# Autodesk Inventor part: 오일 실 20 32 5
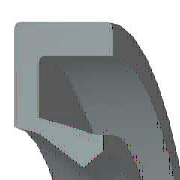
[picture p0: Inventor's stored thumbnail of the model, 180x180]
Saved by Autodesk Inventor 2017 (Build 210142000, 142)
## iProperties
IsCustomPart: 0
Created: 2012-02
Part Number: 오일 실 20 32 5
Material: 고무
Description: 오일 실 - 비스프링, 조립 GA
Document SubType Name: Modeling
Standard: JIS B 2402
Designer: mduedu
Standards Organization: JIS
Language: ko-KR
Size Designation: 20 32 5 A
Categories: <MemberInstance><Categories><Category DisplayName="샤프트 부품" InternalName="7f7aeb1f-a693-4053-b835-cee3144e0d98" Mnemonic="SHFT"><Category DisplayName="실링" Intern
Density: 0.93 g/cm^3
Appearance: Rubber-Black
Author: mduedu
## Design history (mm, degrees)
fillet "모깎기2" dims "d33" = 0.5
body "Solid1"
revolve "회전1" stored, may be unused: angle "d27" = 360 deg
fillet "모깎기1" dims "d28" = 0.25 (= 0.05 x b)
sketch "스케치2"
  geometry: L1 (11.971, -3.75)-(12.571, -5); L2 (11.171, -3.438)-(11.971, -3.75); L3 (10, -1.375)-(11.171, -3.438); L4 (10.923, -0.75)-(10, -1.375); L5 (13.6, -4.375)-(10.923, -0.75); L6 (13.6, -0.25)-(13.6, -4.375); L7 (14.8, -0.25)-(13.6, -0.25); L8 (14.8, 0)-(14.8, -0.25); L9 (16, 0)-(14.8, 0); L10 (16, -5)-(16, 0); L11 (12.571, -5)-(16, -5); L12 (0, -9.6)-(0, 1.6) reference; L13 (28, 0)-(14, 0) reference
  constraints: 22 end point, 3 horizontal, 3 vertical
  dimensions: "d2" = 5 distance of L10.start L9.start (= b); "d4" = 1.2 distance of L9.start L8.start (= 0.1 x dd - 0.1 x Diam); "d6" = 0.25 distance of L8.start L7.start (= 0.05 x b); "d8" = 0.92308 horizontal distance of L4.start L3.start (= 0.0769231 x dd - 0.0769231 x Diam); "d10" = 0.625 vertical distance of L5.start L10.start (= 0.125 x b); "d12" = 1.2 distance of L7.start L6.start (= 0.1 x dd - 0.1 x Diam); "d14" = 0.5 vertical distance of L4.start L6.start (= 0.1 x b); "d16" = 3.42857 distance of L1.end L10.start (= 0.285714 x dd - 0.285714 x Diam); "d18" = 0.6 horizontal distance of L1.start L1.end (= 0.05 x dd - 0.05 x Diam); "d20" = 0.625 vertical distance of L4.start L3.start (= 0.125 x b); "d22" = 1.25 vertical distance of L1.start L1.end (= 0.25 x b); "d24" = 0.8 horizontal distance of L2.start L1.start (= 0.0666667 x dd - 0.0666667 x Diam); "d26" = 0.3125 vertical distance of L2.start L1.start (= 0.0625 x b); "d29" = 0 distance between parallel lines of L13 L9; "d30" = 10 distance from line of L3.start L12 (= 0.5 x Diam); "d31" = 16 distance between parallel lines of L12 L10 (= 0.5 x dd)
other parameters: "dd" = 32 [user parameter; used in 7 equation terms], "b" = 5 [user parameter; used in 8 equation terms], "d1" = 8 (derived), "d3" = 2 (derived), "d5" = 0.4 (derived), "d7" = 1.53846 (derived), "d9" = 1 (derived), "d11" = 2 (derived), "d13" = 0.8 (derived), "d15" = 5.71429 (derived), "d17" = 1 (derived), "d19" = 1 (derived), "d21" = 2 (derived), "d23" = 1.33333 (derived), "d25" = 0.5 (derived), "d32" = 0
